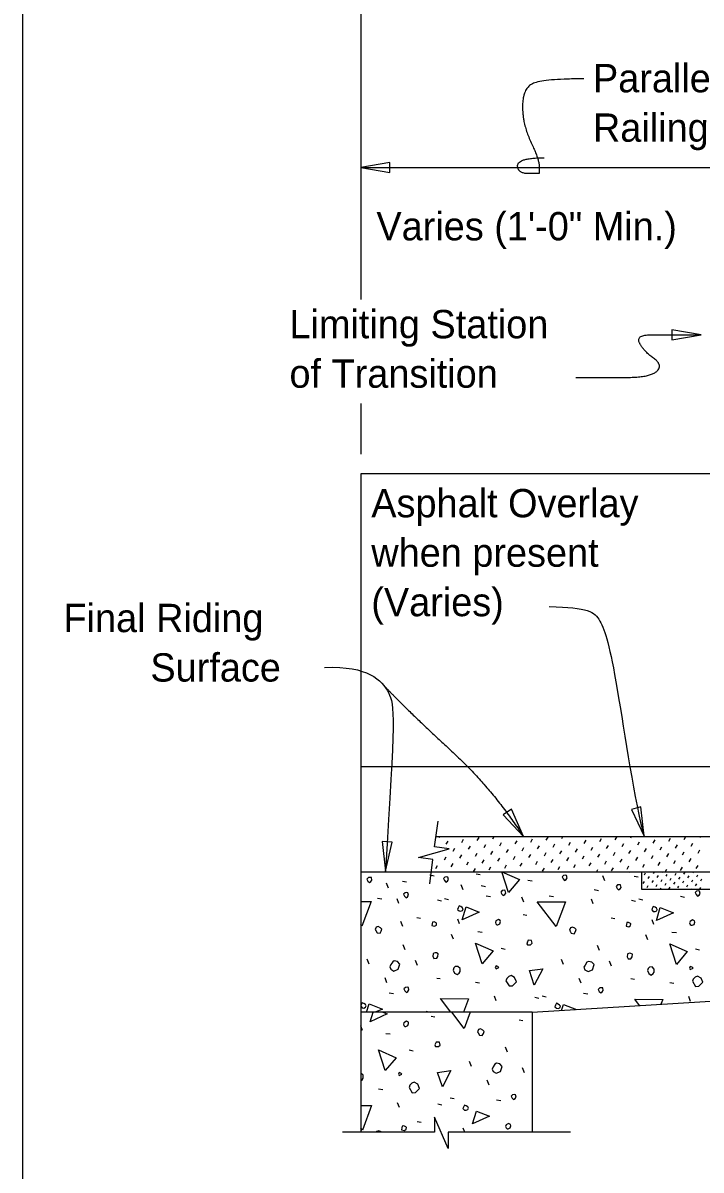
# Model space of a CAD drawing. Extents: x 1.5 to 68.7, y 0 to 31.1.
# Drawn here: x 1.47 to 6.3, y 8.86 to 17.03 of the extents above; entities that cross this region are included whole.
import ezdxf

# ---------------------------------------------------------------- set-up
doc = ezdxf.new("R2010")
doc.units = 0
for name, color, linetype in [('ActivePts-ConstElements', 7, 'Continuous'), ('AdhocPoint_dp', 7, 'Continuous'), ('Patterning', 7, 'Continuous'), ('PlotBorder_dp', 7, 'Continuous'), ('SheetBorder_dp', 7, 'Continuous')]:
    doc.layers.add(name, color=color, linetype=linetype)

msp = doc.modelspace()

# ---------------------------------------------------------------- linework, layer by layer
at = {"layer": 'ActivePts-ConstElements'}
msp.add_lwpolyline([(1.4667, 28.1828), (42.5333, 28.1828), (42.5333, 1.7828), (1.4667, 1.7828)], close=True, dxfattribs=at)
at = {"layer": 'AdhocPoint_dp'}
for p, q in [((3.8717, 19.993), (3.8717, 15.0583)), ((3.8716, 14.3176), (3.8716, 13.9572))]:
    msp.add_line(p, q, dxfattribs=at)
for points in [[(3.8718, 15.9978), (4.08, 15.9625), (4.08, 16.0331)], [(6.2955, 14.8073), (6.0872, 14.8426), (6.0872, 14.772)], [(5.8901, 11.237), (5.8668, 11.4469), (5.799, 11.4275)], [(5.0307, 11.2353), (4.9464, 11.429), (4.8873, 11.3904)], [(4.0475, 10.9895), (4.0958, 11.1951), (4.0253, 11.1995)]]:
    msp.add_lwpolyline(points, close=True, dxfattribs=at)
for points in [[(3.8717, 15.9978), (7.4052, 15.9978)], [(4.3634, 10.8985), (4.3866, 11.0723), (4.2841, 11.0859), (4.3925, 11.1169), (4.5009, 11.1478), (4.3985, 11.1615), (4.4228, 11.3438)], [(5.3648, 9.1297), (4.4956, 9.1297), (4.4956, 9.0135), (4.3963, 9.2385), (4.3963, 9.1297), (3.7411, 9.1297)]]:
    msp.add_lwpolyline(points, dxfattribs=at)
for points, degree in [([(5.4596, 16.6291), (5.1506, 16.6291), (5.0242, 16.5518), (5.0242, 16.3059), (5.1436, 16.053), (5.1436, 15.9547), (5.1436, 15.9547), (4.9891, 15.9547), (4.9891, 16.0671), (5.1787, 16.0671)], 2), ([(5.4027, 14.504), (5.6164, 14.504), (5.9294, 14.504), (6.0287, 14.5885), (5.8846, 14.6929), (5.83, 14.8073), (6.0436, 14.8073), (6.2954, 14.8073)], 2), ([(5.2131, 12.8721), (5.4937, 12.8638), (5.58, 12.8123), (5.6787, 12.479), (5.824, 11.4682), (5.89, 11.2369)], 3), ([(3.6152, 12.4392), (3.9268, 12.4512), (4.1169, 12.247), (4.1169, 12.0935), (4.0474, 10.9894)], 3), ([(4.0341, 12.3137), (4.2082, 12.1286), (4.8016, 11.5859), (5.0307, 11.2353)], 2)]:
    msp.add_open_spline(points, degree=degree, dxfattribs=at)
at = {"layer": 'Patterning'}
for p, q in [((4.4318, 11.2289), (4.435, 11.2345)), ((4.4806, 11.1801), (4.4936, 11.2025)), ((4.5913, 11.193), (4.6042, 11.2154)), ((4.7019, 11.206), (4.7149, 11.2284)), ((4.8125, 11.219), (4.8215, 11.2345)), ((4.8614, 11.1701), (4.8743, 11.1925)), ((4.9232, 11.2319), (4.9246, 11.2345)), ((4.972, 11.1831), (4.985, 11.2055)), ((5.0826, 11.1961), (5.0956, 11.2184)), ((5.1933, 11.209), (5.2062, 11.2314)), ((5.3039, 11.222), (5.3111, 11.2345)), ((5.3527, 11.1731), (5.3657, 11.1955)), ((5.4634, 11.1861), (5.4763, 11.2085)), ((5.574, 11.1991), (5.587, 11.2215)), ((5.6846, 11.212), (5.6976, 11.2344)), ((5.7953, 11.225), (5.8008, 11.2345)), ((5.8441, 11.1762), (5.8571, 11.1986)), ((5.9547, 11.1891), (5.9677, 11.2115)), ((6.0654, 11.2021), (6.0783, 11.2245)), ((6.176, 11.2151), (6.1872, 11.2345)), ((6.2248, 11.1662), (6.2378, 11.1886)), ((6.2866, 11.228), (6.2904, 11.2345)), ((4.5295, 11.1312), (4.5424, 11.1536)), ((4.6401, 11.1442), (4.6531, 11.1666)), ((4.6889, 11.0954), (4.7019, 11.1178)), ((4.7507, 11.1572), (4.7637, 11.1796)), ((4.7996, 11.1083), (4.8125, 11.1307)), ((4.9102, 11.1213), (4.9232, 11.1437)), ((5.0208, 11.1343), (5.0338, 11.1566)), ((5.0697, 11.0854), (5.0826, 11.1078)), ((5.1315, 11.1472), (5.1444, 11.1696)), ((5.1803, 11.0984), (5.1933, 11.1208)), ((5.2421, 11.1602), (5.2551, 11.1826)), ((5.2909, 11.1113), (5.3039, 11.1337)), ((5.4016, 11.1243), (5.4145, 11.1467)), ((5.5122, 11.1373), (5.5252, 11.1597)), ((5.561, 11.0884), (5.574, 11.1108)), ((5.6228, 11.1502), (5.6358, 11.1726)), ((5.6717, 11.1014), (5.6846, 11.1238)), ((5.7335, 11.1632), (5.7464, 11.1856)), ((5.7823, 11.1144), (5.7953, 11.1368)), ((5.8929, 11.1273), (5.9059, 11.1497)), ((6.0036, 11.1403), (6.0165, 11.1627)), ((6.0524, 11.0915), (6.0654, 11.1139)), ((6.1142, 11.1533), (6.1272, 11.1756)), ((6.163, 11.1044), (6.176, 11.1268)), ((6.2737, 11.1174), (6.2866, 11.1398)), ((4.4059, 11.0076), (4.4188, 11.03)), ((4.4677, 11.0694), (4.4806, 11.0918)), ((4.5165, 11.0206), (4.5295, 11.043)), ((4.5783, 11.0824), (4.5913, 11.1048)), ((4.6271, 11.0336), (4.6401, 11.056)), ((4.7378, 11.0465), (4.7507, 11.0689)), ((4.8484, 11.0595), (4.8614, 11.0819)), ((4.8972, 11.0107), (4.9102, 11.0331)), ((4.959, 11.0725), (4.972, 11.0948)), ((5.0079, 11.0236), (5.0208, 11.046)), ((5.1185, 11.0366), (5.1315, 11.059)), ((5.2291, 11.0495), (5.2421, 11.0719)), ((5.3398, 11.0625), (5.3527, 11.0849)), ((5.3886, 11.0137), (5.4016, 11.0361)), ((5.4504, 11.0755), (5.4634, 11.0979)), ((5.4992, 11.0266), (5.5122, 11.049)), ((5.6099, 11.0396), (5.6228, 11.062)), ((5.7205, 11.0526), (5.7335, 11.075)), ((5.7693, 11.0037), (5.7823, 11.0261)), ((5.8311, 11.0655), (5.8441, 11.0879)), ((5.88, 11.0167), (5.8929, 11.0391)), ((5.9418, 11.0785), (5.9547, 11.1009)), ((5.9906, 11.0297), (6.0036, 11.0521)), ((6.1012, 11.0426), (6.1142, 11.065)), ((6.2119, 11.0556), (6.2248, 11.078)), ((6.2607, 11.0068), (6.2737, 11.0291)), ((4.3648, 10.9618), (4.3948, 10.9565)), ((4.676, 10.9847), (4.6889, 11.0071)), ((4.6932, 10.9698), (4.7233, 10.9645)), ((4.7866, 10.9977), (4.7996, 11.0201)), ((5.1673, 10.9878), (5.1803, 11.0101)), ((5.278, 11.0007), (5.2909, 11.0231)), ((5.5503, 10.9816), (5.561, 11.0002)), ((5.6106, 10.9206), (5.5965, 10.9559)), ((5.6587, 10.9908), (5.6717, 11.0132)), ((5.7804, 10.9798), (5.7831, 10.9845)), ((5.8186, 10.9538), (5.8486, 10.9485)), ((5.8922, 10.9636), (5.9003, 10.9776)), ((5.9199, 10.9359), (5.928, 10.9499)), ((5.9557, 10.9717), (5.963, 10.9845)), ((5.9834, 10.944), (5.9915, 10.958)), ((6.0191, 10.9798), (6.0218, 10.9845)), ((6.0399, 10.9816), (6.0524, 11.0032)), ((6.0468, 10.9521), (6.0549, 10.9661)), ((6.1103, 10.9602), (6.1184, 10.9742)), ((6.138, 10.9325), (6.1461, 10.9465)), ((6.1501, 10.9938), (6.163, 11.0162)), ((6.1738, 10.9683), (6.1819, 10.9823)), ((6.2015, 10.9406), (6.2096, 10.9546)), ((6.2373, 10.9764), (6.242, 10.9845)), ((6.265, 10.9487), (6.2731, 10.9627)), ((6.2802, 10.9811), (6.2821, 10.9845)), ((4.0687, 10.8685), (4.0546, 10.9038)), ((4.1686, 10.9177), (4.1986, 10.9124)), ((4.6014, 10.8564), (4.5872, 10.8918)), ((4.7292, 10.8857), (4.7593, 10.8804)), ((5.0617, 10.9258), (5.0917, 10.9205)), ((5.8841, 10.9001), (5.8922, 10.9141)), ((5.9118, 10.8724), (5.9199, 10.8864)), ((5.9476, 10.9082), (5.9557, 10.9222)), ((5.9752, 10.8805), (5.9834, 10.8945)), ((6.0068, 10.8595), (6.011, 10.8668)), ((6.011, 10.9163), (6.0191, 10.9303)), ((6.0387, 10.8886), (6.0468, 10.9026)), ((6.0664, 10.8609), (6.0745, 10.8749)), ((6.0745, 10.9244), (6.0826, 10.9384)), ((6.1022, 10.8967), (6.1103, 10.9107)), ((6.1299, 10.869), (6.138, 10.883)), ((6.1657, 10.9048), (6.1738, 10.9188)), ((6.1934, 10.8771), (6.2015, 10.8911)), ((6.2269, 10.8595), (6.2292, 10.8634)), ((6.2292, 10.9129), (6.2373, 10.9269)), ((6.2569, 10.8852), (6.265, 10.8992)), ((6.2857, 10.8595), (6.2927, 10.8715)), ((6.2927, 10.921), (6.3008, 10.935)), ((3.9923, 10.7975), (4.0224, 10.7922)), ((4.1439, 10.7587), (4.1315, 10.7923)), ((4.4179, 10.7852), (4.4462, 10.7782)), ((4.4696, 10.7945), (4.4979, 10.7875)), ((4.7653, 10.8135), (4.7953, 10.8082)), ((5.0339, 10.7683), (5.0197, 10.8036)), ((5.2138, 10.8135), (5.2439, 10.8082)), ((5.5272, 10.7552), (5.5148, 10.7888)), ((5.5342, 10.8576), (5.5643, 10.8523)), ((5.8012, 10.7817), (5.8295, 10.7746)), ((5.8529, 10.791), (5.8812, 10.7839)), ((6.1486, 10.81), (6.1786, 10.8047)), ((4.1728, 10.5959), (4.1587, 10.6313)), ((4.2712, 10.6597), (4.2977, 10.6544)), ((4.5757, 10.6133), (4.5633, 10.6469)), ((5.0287, 10.6809), (5.0552, 10.6756)), ((5.6545, 10.6562), (5.681, 10.6509)), ((5.959, 10.6098), (5.9466, 10.6434)), ((4.5333, 10.5037), (4.5191, 10.5391)), ((4.7052, 10.559), (4.737, 10.5554)), ((5.9165, 10.5002), (5.9024, 10.5355)), ((6.0885, 10.5554), (6.1203, 10.5519)), ((4.1881, 10.4282), (4.174, 10.4635)), ((5.5714, 10.4246), (5.5572, 10.46)), ((4.8731, 10.4405), (4.9014, 10.4335)), ((6.2564, 10.437), (6.2847, 10.4299)), ((3.9318, 10.3274), (3.9176, 10.3627)), ((4.2752, 10.3163), (4.261, 10.3517)), ((5.3151, 10.3239), (5.3009, 10.3592)), ((5.6585, 10.3128), (5.6443, 10.3482)), ((4.0573, 10.1948), (4.0449, 10.2284)), ((4.4131, 10.228), (4.4378, 10.2244)), ((5.4406, 10.1913), (5.4282, 10.2249)), ((5.7963, 10.2244), (5.8211, 10.2209)), ((4.6888, 10.1997), (4.7189, 10.1944)), ((6.0721, 10.1961), (6.1022, 10.1908)), ((4.0754, 10.1237), (4.1055, 10.1184)), ((4.8373, 10.0653), (4.825, 10.0989)), ((5.1113, 10.0918), (5.1396, 10.0848)), ((5.163, 10.1011), (5.1913, 10.094)), ((5.4587, 10.1201), (5.4887, 10.1148)), ((6.2206, 10.0618), (6.2082, 10.0954)), ((4.3388, 9.9911), (4.3653, 9.9858)), ((4.3388, 9.9911), (4.3653, 9.9858)), ((3.8858, 9.8536), (3.8734, 9.8872)), ((4.3737, 9.9562), (4.4002, 9.9509)), ((4.9995, 9.9314), (5.026, 9.9261)), ((4.0502, 9.8342), (4.082, 9.8307)), ((4.9164, 9.6998), (4.9023, 9.7352)), ((4.2181, 9.7157), (4.2464, 9.7087)), ((4.6601, 9.5991), (4.6459, 9.6344)), ((5.0384, 9.5531), (5.0242, 9.5885)), ((4.7856, 9.4665), (4.7732, 9.5001)), ((3.9989, 9.44), (4.029, 9.4347)), ((4.1474, 9.3056), (4.135, 9.3392)), ((4.4214, 9.3321), (4.4497, 9.3251)), ((4.508, 9.3763), (4.5363, 9.3693)), ((4.8386, 9.3604), (4.8687, 9.3551)), ((4.2747, 9.2066), (4.3012, 9.2013)), ((4.6125, 9.1297), (4.6017, 9.1589))]:
    msp.add_line(p, q, dxfattribs=at)
for points in [[(3.9235, 10.9181), (3.9341, 10.9075), (3.9447, 10.9146), (3.9518, 10.9252), (3.9482, 10.9428), (3.9394, 10.9446), (3.927, 10.9428), (3.9164, 10.9322), (3.9235, 10.9181)], [(4.4682, 10.9221), (4.4788, 10.9115), (4.4894, 10.9186), (4.4964, 10.9292), (4.4929, 10.9468), (4.4841, 10.9486), (4.4717, 10.9468), (4.4611, 10.9362), (4.4682, 10.9221)], [(4.9248, 10.8378), (4.8771, 10.9845), (5.0026, 10.9297), (4.9248, 10.8378)], [(5.3132, 10.9341), (5.3238, 10.9235), (5.3344, 10.9306), (5.3415, 10.9412), (5.3379, 10.9589), (5.3291, 10.9606), (5.3167, 10.9589), (5.3061, 10.9483), (5.3132, 10.9341)], [(5.6977, 10.866), (5.7083, 10.8554), (5.7189, 10.8624), (5.726, 10.8731), (5.7224, 10.8907), (5.7136, 10.8925), (5.7012, 10.8907), (5.6906, 10.8801), (5.6977, 10.866)], [(4.1838, 10.8099), (4.1944, 10.7993), (4.205, 10.8063), (4.2121, 10.8169), (4.2086, 10.8346), (4.1997, 10.8364), (4.1873, 10.8346), (4.1767, 10.824), (4.1838, 10.8099)], [(4.8767, 10.8259), (4.8873, 10.8153), (4.8979, 10.8224), (4.9049, 10.833), (4.9014, 10.8507), (4.8926, 10.8524), (4.8802, 10.8507), (4.8696, 10.84), (4.8767, 10.8259)], [(6.2599, 10.8224), (6.2705, 10.8118), (6.2811, 10.8188), (6.2882, 10.8294), (6.2847, 10.8471), (6.2758, 10.8489), (6.2635, 10.8471), (6.2529, 10.8365), (6.2599, 10.8224)], [(3.8717, 10.7735), (3.9459, 10.7729), (3.8805, 10.5979)], [(4.5722, 10.7061), (4.5845, 10.7044), (4.5969, 10.7097), (4.6004, 10.7203), (4.5951, 10.7291), (4.5845, 10.7362), (4.5722, 10.7415), (4.5651, 10.7273), (4.5616, 10.7167), (4.5722, 10.7061)], [(4.5938, 10.6421), (4.6221, 10.734), (4.7158, 10.6969), (4.5938, 10.6421)], [(5.2638, 10.5943), (5.1294, 10.7711), (5.3292, 10.7693), (5.2638, 10.5943)], [(5.9554, 10.7026), (5.9678, 10.7008), (5.9802, 10.7061), (5.9837, 10.7167), (5.9784, 10.7256), (5.9678, 10.7327), (5.9554, 10.738), (5.9484, 10.7238), (5.9448, 10.7132), (5.9554, 10.7026)], [(5.9771, 10.6385), (6.0054, 10.7304), (6.0991, 10.6933), (5.9771, 10.6385)], [(4.379, 10.6014), (4.3985, 10.5961), (4.4109, 10.6049), (4.4126, 10.6173), (4.4091, 10.6208), (4.3949, 10.6279), (4.3826, 10.6261), (4.3808, 10.6138), (4.379, 10.6014)], [(4.8413, 10.6067), (4.8484, 10.6067), (4.8625, 10.6138), (4.8678, 10.6297), (4.8661, 10.6385), (4.8519, 10.6456), (4.8342, 10.635), (4.8307, 10.6244), (4.8342, 10.6138), (4.8413, 10.6067)], [(5.7623, 10.5979), (5.7818, 10.5926), (5.7941, 10.6014), (5.7959, 10.6138), (5.7924, 10.6173), (5.7782, 10.6244), (5.7658, 10.6226), (5.7641, 10.6102), (5.7623, 10.5979)], [(6.2246, 10.6032), (6.2317, 10.6032), (6.2458, 10.6102), (6.2511, 10.6261), (6.2493, 10.635), (6.2352, 10.6421), (6.2175, 10.6314), (6.214, 10.6208), (6.2175, 10.6102), (6.2246, 10.6032)], [(3.8805, 10.5979), (3.8717, 10.6095)], [(3.9795, 10.566), (3.9884, 10.5501), (4.0096, 10.5466), (4.0184, 10.5625), (4.0219, 10.5766), (4.0131, 10.5855), (3.9972, 10.5943), (3.9813, 10.589), (3.976, 10.5731), (3.9795, 10.566)], [(5.3628, 10.5625), (5.3716, 10.5466), (5.3928, 10.5431), (5.4017, 10.559), (5.4052, 10.5731), (5.3964, 10.582), (5.3805, 10.5908), (5.3646, 10.5855), (5.3593, 10.5696), (5.3628, 10.5625)], [(4.7366, 10.3287), (4.6888, 10.4754), (4.8143, 10.4206), (4.7366, 10.3287)], [(5.0605, 10.4653), (5.0817, 10.4653), (5.0923, 10.4759), (5.087, 10.4953), (5.064, 10.4971), (5.0605, 10.4865), (5.0552, 10.4777), (5.0605, 10.4653), (5.057, 10.4688)], [(6.1198, 10.3252), (6.0721, 10.4719), (6.1976, 10.4171), (6.1198, 10.3252)], [(4.3848, 10.3835), (4.3936, 10.3676), (4.4131, 10.3694), (4.4219, 10.3818), (4.4237, 10.4012), (4.4113, 10.4065), (4.4025, 10.4083), (4.3918, 10.4047), (4.3883, 10.4012), (4.3848, 10.3835)], [(5.7681, 10.38), (5.7769, 10.3641), (5.7963, 10.3658), (5.8052, 10.3782), (5.8069, 10.3977), (5.7946, 10.403), (5.7857, 10.4047), (5.7751, 10.4012), (5.7716, 10.3977), (5.7681, 10.38)], [(4.0856, 10.2903), (4.1086, 10.2779), (4.1386, 10.2903), (4.151, 10.3274), (4.1333, 10.3451), (4.1103, 10.3504), (4.0997, 10.3433), (4.0874, 10.3239), (4.0785, 10.3079), (4.0856, 10.2903)], [(4.5297, 10.2845), (4.5403, 10.2633), (4.558, 10.2527), (4.5722, 10.2633), (4.5792, 10.2739), (4.5792, 10.2951), (4.5633, 10.311), (4.5439, 10.3093), (4.535, 10.3004), (4.5297, 10.2845)], [(4.8356, 10.2934), (4.855, 10.3022), (4.8479, 10.3093), (4.8356, 10.3146), (4.8303, 10.3022), (4.8356, 10.2934)], [(5.1082, 10.1771), (5.0746, 10.2814), (5.1683, 10.2938), (5.1082, 10.1771)], [(5.4689, 10.2867), (5.4918, 10.2744), (5.5219, 10.2867), (5.5343, 10.3239), (5.5166, 10.3415), (5.4936, 10.3468), (5.483, 10.3398), (5.4706, 10.3203), (5.4618, 10.3044), (5.4689, 10.2867)], [(5.913, 10.281), (5.9236, 10.2598), (5.9413, 10.2492), (5.9554, 10.2598), (5.9625, 10.2704), (5.9625, 10.2916), (5.9466, 10.3075), (5.9272, 10.3057), (5.9183, 10.2969), (5.913, 10.281)], [(6.2188, 10.2898), (6.2383, 10.2987), (6.2312, 10.3057), (6.2188, 10.311), (6.2135, 10.2987), (6.2188, 10.2898)], [(4.9063, 10.2085), (4.9292, 10.1714), (4.9522, 10.1732), (4.9611, 10.182), (4.9805, 10.2014), (4.9681, 10.2315), (4.9434, 10.2456), (4.9257, 10.2386), (4.9116, 10.2244), (4.9063, 10.2085)], [(6.2339, 10.205), (6.2568, 10.1679), (6.2798, 10.1696), (6.2887, 10.1785), (6.3081, 10.1979), (6.2957, 10.228), (6.271, 10.2421), (6.2533, 10.235), (6.2392, 10.2209), (6.2339, 10.205)], [(4.1868, 10.136), (4.1974, 10.1254), (4.208, 10.1325), (4.2151, 10.1431), (4.2115, 10.1608), (4.2027, 10.1625), (4.1903, 10.1608), (4.1797, 10.1502), (4.1868, 10.136)], [(5.5701, 10.1325), (5.5807, 10.1219), (5.5913, 10.129), (5.5983, 10.1396), (5.5948, 10.1572), (5.586, 10.159), (5.5736, 10.1572), (5.563, 10.1466), (5.5701, 10.1325)], [(3.8823, 10.0163), (3.8947, 10.0145), (3.907, 10.0198), (3.9106, 10.0304), (3.9053, 10.0392), (3.8947, 10.0463), (3.8823, 10.0516), (3.8752, 10.0375), (3.8717, 10.0269)], [(4.5131, 9.9844), (4.4396, 10.0812), (4.6393, 10.0795), (4.6038, 9.9844)], [(5.2656, 10.0127), (5.2779, 10.011), (5.2903, 10.0163), (5.2939, 10.0269), (5.2885, 10.0357), (5.2779, 10.0428), (5.2656, 10.0481), (5.2585, 10.0339), (5.255, 10.0233), (5.2656, 10.0127)], [(5.8574, 10.0323), (5.8229, 10.0777), (6.0226, 10.0759), (6.0099, 10.0418)], [(3.8717, 10.0269), (3.8823, 10.0163)], [(3.9139, 9.9844), (3.9322, 10.0441), (4.0259, 10.007), (3.9758, 9.9844)], [(3.9388, 9.9173), (3.9595, 9.9844)], [(4.0296, 9.9844), (4.0608, 9.9721), (3.9388, 9.9173)], [(4.6088, 9.8695), (4.5215, 9.9844)], [(4.6517, 9.9844), (4.6088, 9.8695)], [(5.3023, 9.9976), (5.3155, 10.0406), (5.4074, 10.0042)], [(4.1863, 9.8819), (4.1934, 9.8819), (4.2075, 9.889), (4.2128, 9.9049), (4.2111, 9.9137), (4.1969, 9.9208), (4.1792, 9.9102), (4.1757, 9.8996), (4.1792, 9.889), (4.1863, 9.8819)], [(4.7078, 9.8377), (4.7166, 9.8218), (4.7379, 9.8183), (4.7467, 9.8342), (4.7502, 9.8483), (4.7414, 9.8572), (4.7255, 9.866), (4.7096, 9.8607), (4.7043, 9.8448), (4.7078, 9.8377)], [(4.4055, 9.7405), (4.4267, 9.7405), (4.4373, 9.7511), (4.432, 9.7705), (4.409, 9.7723), (4.4055, 9.7617), (4.4002, 9.7529), (4.4055, 9.7405), (4.402, 9.744)], [(4.0467, 9.569), (3.9989, 9.7157), (4.1244, 9.6609), (4.0467, 9.569)], [(4.1456, 9.5337), (4.1651, 9.5425), (4.158, 9.5496), (4.1456, 9.5549), (4.1403, 9.5425), (4.1456, 9.5337)], [(4.4532, 9.4524), (4.4197, 9.5566), (4.5133, 9.569), (4.4532, 9.4524)], [(4.8139, 9.562), (4.8368, 9.5496), (4.8669, 9.562), (4.8793, 9.5991), (4.8616, 9.6168), (4.8386, 9.6221), (4.828, 9.615), (4.8156, 9.5955), (4.8068, 9.5796), (4.8139, 9.562)], [(3.8717, 9.4957), (3.8823, 9.5036), (3.8893, 9.5142), (3.8893, 9.5354), (3.8734, 9.5513), (3.8717, 9.5512)], [(4.2164, 9.4488), (4.2393, 9.4117), (4.2623, 9.4135), (4.2712, 9.4223), (4.2906, 9.4417), (4.2782, 9.4718), (4.2535, 9.4859), (4.2358, 9.4789), (4.2217, 9.4647), (4.2164, 9.4488)], [(4.95, 9.3728), (4.9606, 9.3622), (4.9712, 9.3693), (4.9783, 9.3799), (4.9747, 9.3975), (4.9659, 9.3993), (4.9535, 9.3975), (4.9429, 9.3869), (4.95, 9.3728)], [(3.8717, 9.3205), (3.9494, 9.3198), (3.884, 9.1448)], [(4.6106, 9.2879), (4.6229, 9.2862), (4.6353, 9.2915), (4.6389, 9.3021), (4.6336, 9.3109), (4.6229, 9.318), (4.6106, 9.3233), (4.6035, 9.3092), (4.6, 9.2986), (4.6106, 9.2879)], [(4.6671, 9.189), (4.6954, 9.2809), (4.7891, 9.2438), (4.6671, 9.189)], [(3.884, 9.1448), (3.8717, 9.161)], [(4.1635, 9.1483), (4.1829, 9.143), (4.1953, 9.1518), (4.1971, 9.1642), (4.1935, 9.1677), (4.1794, 9.1748), (4.167, 9.173), (4.1653, 9.1607), (4.1635, 9.1483)], [(4.9146, 9.1536), (4.9217, 9.1536), (4.9358, 9.1607), (4.9411, 9.1766), (4.9394, 9.1854), (4.9252, 9.1925), (4.9076, 9.1819), (4.904, 9.1713), (4.9076, 9.1607), (4.9146, 9.1536)], [(4.0193, 9.1297), (4.0166, 9.1324), (4.0007, 9.1412), (3.9848, 9.1359), (3.9827, 9.1297)]]:
    msp.add_lwpolyline(points, dxfattribs=at)
at = {"layer": 'PlotBorder_dp'}
for p, q in [((3.8717, 13.8178), (3.8717, 11.7345)), ((14.1461, 13.8178), (3.8717, 13.8178)), ((3.8717, 11.7345), (14.1461, 11.7345)), ((3.8718, 11.7345), (3.8718, 9.1297)), ((4.4082, 11.2345), (6.67, 11.2345)), ((3.8717, 10.9845), (18.1441, 10.9845)), ((5.8718, 10.9845), (5.8718, 10.8595)), ((5.8718, 10.8595), (11.8162, 10.8595)), ((5.0917, 9.9844), (9.0917, 10.2344)), ((5.0917, 9.9845), (3.8717, 9.9845)), ((5.0918, 9.9845), (5.0918, 9.1297)), ((5.0918, 9.9844), (5.0918, 9.1297))]:
    msp.add_line(p, q, dxfattribs=at)

# ---------------------------------------------------------------- texts
at = {"layer": 'AdhocPoint_dp'}
for s, p in [('Parallel Portion of Vertical Face Retrofit ', (5.5257, 16.5332)), ('Railing if present (See Note 1)', (5.5257, 16.1812)), ('Limiting Station', (3.3647, 14.7822)), ('of Transition', (3.3647, 14.4302)), ('Asphalt Overlay', (3.9472, 13.5078)), ('when present', (3.9472, 13.1558)), ('(Varies)', (3.9472, 12.8038)), ('Final Riding ', (1.7555, 12.6904)), ('Surface', (2.3743, 12.3384))]:
    msp.add_text(s, height=0.2016, dxfattribs=at).set_placement(p)
at = {"layer": 'SheetBorder_dp'}
msp.add_text('Varies (1\'-0" Min.)', height=0.2016, dxfattribs=at).set_placement((3.9837, 15.4794))

doc.saveas('drawing.dxf')
